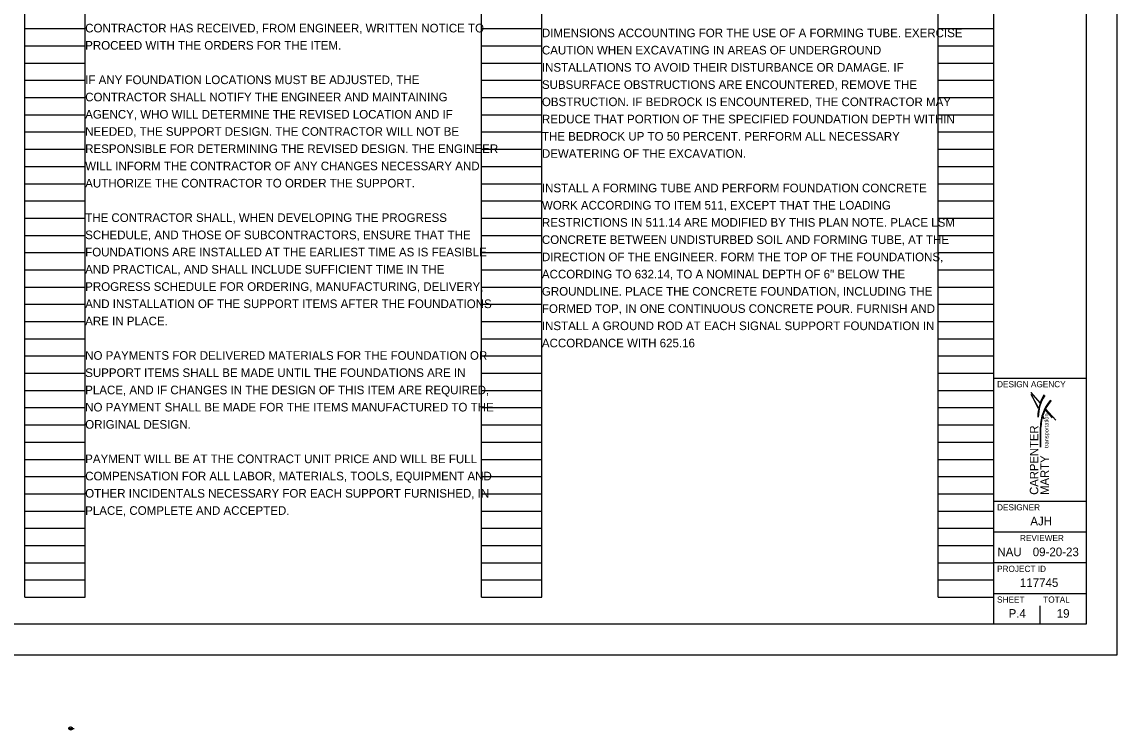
# Model space of a CAD drawing. Extents: x 0 to 34, y -1.2 to 22.
# Drawn here: x 16.21 to 34, y -1.18 to 10.33 of the extents above; entities that cross this region are included whole.
import ezdxf

# ---------------------------------------------------------------- set-up
doc = ezdxf.new("R2010")
doc.units = 0
for name, color, linetype in [('SH_Border', 7, 'Continuous'), ('SH_Cut_Line', 7, 'Continuous'), ('SH_Data', 7, 'Continuous'), ('SH_Text', 7, 'Continuous')]:
    doc.layers.add(name, color=color, linetype=linetype)

msp = doc.modelspace()

# ---------------------------------------------------------------- linework, layer by layer
at = {"layer": 'SH_Border'}
for p, q in [((32.005, 0.541), (32.005, 21.541)), ((32.005, 4.541), (33.505, 4.541)), ((32.005, 2.541), (33.505, 2.541)), ((32.005, 2.041), (33.505, 2.041)), ((32.005, 1.541), (33.505, 1.541)), ((32.005, 1.041), (33.505, 1.041))]:
    msp.add_line(p, q, dxfattribs=at)
msp.add_lwpolyline([(1.505, 21.541), (33.505, 21.541), (33.505, 0.541), (1.505, 0.541)], close=True, dxfattribs=at)
at = {"layer": 'SH_Cut_Line'}
msp.add_lwpolyline([(0.005, 0.041), (34.005, 0.041), (34.005, 22.041), (0.005, 22.041)], close=True, dxfattribs=at)
at = {"layer": 'SH_Data'}
for p, q in [((16.26, 0.98), (16.26, 21.14)), ((17.24, 0.98), (17.24, 21.14)), ((23.68, 0.98), (23.68, 21.14)), ((24.66, 0.98), (24.66, 21.14)), ((31.1, 0.98), (31.1, 21.14)), ((32, 0.98), (32, 21.14)), ((16.26, 10.22), (17.24, 10.22)), ((23.68, 10.22), (24.66, 10.22)), ((31.1, 10.22), (32, 10.22)), ((16.26, 9.94), (17.24, 9.94)), ((23.68, 9.94), (24.66, 9.94)), ((31.1, 9.94), (32, 9.94)), ((16.26, 9.66), (17.24, 9.66)), ((23.68, 9.66), (24.66, 9.66)), ((31.1, 9.66), (32, 9.66)), ((16.26, 9.38), (17.24, 9.38)), ((23.68, 9.38), (24.66, 9.38)), ((31.1, 9.38), (32, 9.38)), ((16.26, 9.1), (17.24, 9.1)), ((23.68, 9.1), (24.66, 9.1)), ((31.1, 9.1), (32, 9.1)), ((16.26, 8.82), (17.24, 8.82)), ((23.68, 8.82), (24.66, 8.82)), ((31.1, 8.82), (32, 8.82)), ((16.26, 8.54), (17.24, 8.54)), ((23.68, 8.54), (24.66, 8.54)), ((31.1, 8.54), (32, 8.54)), ((16.26, 8.26), (17.24, 8.26)), ((23.68, 8.26), (24.66, 8.26)), ((31.1, 8.26), (32, 8.26)), ((16.26, 7.98), (17.24, 7.98)), ((23.68, 7.98), (24.66, 7.98)), ((31.1, 7.98), (32, 7.98)), ((16.26, 7.7), (17.24, 7.7)), ((23.68, 7.7), (24.66, 7.7)), ((31.1, 7.7), (32, 7.7)), ((16.26, 7.42), (17.24, 7.42)), ((23.68, 7.42), (24.66, 7.42)), ((31.1, 7.42), (32, 7.42)), ((16.26, 7.14), (17.24, 7.14)), ((23.68, 7.14), (24.66, 7.14)), ((31.1, 7.14), (32, 7.14)), ((16.26, 6.86), (17.24, 6.86)), ((23.68, 6.86), (24.66, 6.86)), ((31.1, 6.86), (32, 6.86)), ((16.26, 6.58), (17.24, 6.58)), ((23.68, 6.58), (24.66, 6.58)), ((31.1, 6.58), (32, 6.58)), ((16.26, 6.3), (17.24, 6.3)), ((23.68, 6.3), (24.66, 6.3)), ((31.1, 6.3), (32, 6.3)), ((16.26, 6.02), (17.24, 6.02)), ((23.68, 6.02), (24.66, 6.02)), ((31.1, 6.02), (32, 6.02)), ((16.26, 5.74), (17.24, 5.74)), ((23.68, 5.74), (24.66, 5.74)), ((31.1, 5.74), (32, 5.74)), ((16.26, 5.46), (17.24, 5.46)), ((23.68, 5.46), (24.66, 5.46)), ((31.1, 5.46), (32, 5.46)), ((16.26, 5.18), (17.24, 5.18)), ((23.68, 5.18), (24.66, 5.18)), ((31.1, 5.18), (32, 5.18)), ((16.26, 4.9), (17.24, 4.9)), ((23.68, 4.9), (24.66, 4.9)), ((31.1, 4.9), (32, 4.9)), ((16.26, 4.62), (17.24, 4.62)), ((23.68, 4.62), (24.66, 4.62)), ((31.1, 4.62), (32, 4.62)), ((16.26, 4.34), (17.24, 4.34)), ((23.68, 4.34), (24.66, 4.34)), ((31.1, 4.34), (32, 4.34)), ((16.26, 4.06), (17.24, 4.06)), ((23.68, 4.06), (24.66, 4.06)), ((31.1, 4.06), (32, 4.06)), ((16.26, 3.78), (17.24, 3.78)), ((23.68, 3.78), (24.66, 3.78)), ((31.1, 3.78), (32, 3.78)), ((16.26, 3.5), (17.24, 3.5)), ((23.68, 3.5), (24.66, 3.5)), ((31.1, 3.5), (32, 3.5)), ((32.755, 3.541), (32.755, 3.541)), ((16.26, 3.22), (17.24, 3.22)), ((23.68, 3.22), (24.66, 3.22)), ((31.1, 3.22), (32, 3.22)), ((16.26, 2.94), (17.24, 2.94)), ((23.68, 2.94), (24.66, 2.94)), ((31.1, 2.94), (32, 2.94)), ((16.26, 2.66), (17.24, 2.66)), ((23.68, 2.66), (24.66, 2.66)), ((31.1, 2.66), (32, 2.66)), ((16.26, 2.38), (17.24, 2.38)), ((23.68, 2.38), (24.66, 2.38)), ((31.1, 2.38), (32, 2.38)), ((16.26, 2.1), (17.24, 2.1)), ((23.68, 2.1), (24.66, 2.1)), ((31.1, 2.1), (32, 2.1)), ((16.26, 1.82), (17.24, 1.82)), ((23.68, 1.82), (24.66, 1.82)), ((31.1, 1.82), (32, 1.82)), ((16.26, 1.54), (17.24, 1.54)), ((23.68, 1.54), (24.66, 1.54)), ((31.1, 1.54), (32, 1.54)), ((16.26, 1.26), (17.24, 1.26)), ((23.68, 1.26), (24.66, 1.26)), ((31.1, 1.26), (32, 1.26)), ((16.26, 0.98), (17.24, 0.98)), ((23.68, 0.98), (24.66, 0.98)), ((31.1, 0.98), (32, 0.98)), ((32.38, 0.716), (32.38, 0.716)), ((32.755, 0.541), (32.755, 0.841)), ((16.98, -1.154), (17.032, -1.154)), ((17.006, -1.154), (17.059, -1.154))]:
    msp.add_line(p, q, dxfattribs=at)
msp.add_circle((17.006, -1.154), 0.026, dxfattribs=at)
at = {"layer": 'SH_Text'}
for p, q in [((32.726, 4.057), (32.607, 4.273)), ((32.816, 3.881), (32.795, 3.921)), ((32.825, 3.874), (32.796, 3.927)), ((32.957, 3.893), (32.839, 4.032)), ((32.844, 4.042), (33.011, 3.857)), ((32.76, 3.418), (32.76, 3.745)), ((32.767, 3.418), (32.767, 3.745)), ((16.974, -1.152), (17.026, -1.152)), ((17, -1.152), (17.049, -1.152))]:
    msp.add_line(p, q, dxfattribs=at)
for points in [[(32.751, 4.145), (32.606, 4.307)], [(32.606, 4.307), (32.749, 4.139)], [(32.726, 4.057), (32.607, 4.273)], [(32.607, 4.272), (32.724, 4.052)]]:
    msp.add_lwpolyline(points, dxfattribs=at)
msp.add_circle((17, -1.152), 0.026, dxfattribs=at)
for centre, radius, start, end in [((33.437, 3.901), 0.721, 149.5704, 179.5529), ((33.378, 3.902), 0.654, 147.1423, 179.6525), ((33.431, 3.745), 0.671, 139.2898, 180.0106), ((33.438, 3.729), 0.672, 138.5126, 178.6075)]:
    msp.add_arc(centre, radius, start, end, dxfattribs=at)

# ---------------------------------------------------------------- texts
at = {"layer": 'SH_Data'}
for s, height, p in [('DESIGN AGENCY', 0.1, (32.055, 4.391)), ('DESIGNER', 0.1, (32.055, 2.391)), ('AJH', 0.14, (32.595, 2.146)), ('REVIEWER', 0.1, (32.427, 1.891)), ('NAU', 0.14, (32.06, 1.646)), ('09-20-23', 0.14, (32.634, 1.646)), ('PROJECT ID', 0.1, (32.055, 1.391)), ('117745', 0.14, (32.426, 1.146)), ('SHEET', 0.1, (32.055, 0.891)), ('TOTAL', 0.1, (32.805, 0.891)), ('P.4', 0.14, (32.242, 0.646)), ('19', 0.14, (33.024, 0.646)), ('P.4', 0.00328, (17.003, -1.164)), ('2', 0.00328, (17.004, -1.148)), ('Drawing-1', 0.00328, (17.038, -1.148)), ('1:1', 0.00328, (17.038, -1.164))]:
    msp.add_text(s, height=height, dxfattribs=at).set_placement(p)
at = {"layer": 'SH_Text'}
for s, height, p in [('CONTRACTOR HAS RECEIVED, FROM ENGINEER, WRITTEN NOTICE TO ', 0.14, (17.24, 10.158)), ('DIMENSIONS ACCOUNTING FOR THE USE OF A FORMING TUBE. EXERCISE ', 0.14, (24.66, 10.08)), ('PROCEED WITH THE ORDERS FOR THE ITEM. ', 0.14, (17.24, 9.878)), ('CAUTION WHEN EXCAVATING IN AREAS OF UNDERGROUND ', 0.14, (24.66, 9.8)), ('INSTALLATIONS TO AVOID THEIR DISTURBANCE OR DAMAGE. IF ', 0.14, (24.66, 9.52)), ('IF ANY FOUNDATION LOCATIONS MUST BE ADJUSTED, THE ', 0.14, (17.24, 9.318)), ('SUBSURFACE OBSTRUCTIONS ARE ENCOUNTERED, REMOVE THE ', 0.14, (24.66, 9.24)), ('CONTRACTOR SHALL NOTIFY THE ENGINEER AND MAINTAINING ', 0.14, (17.24, 9.038)), ('OBSTRUCTION. IF BEDROCK IS ENCOUNTERED, THE CONTRACTOR MAY ', 0.14, (24.66, 8.96)), ('AGENCY, WHO WILL DETERMINE THE REVISED LOCATION AND IF ', 0.14, (17.24, 8.758)), ('REDUCE THAT PORTION OF THE SPECIFIED FOUNDATION DEPTH WITHIN ', 0.14, (24.66, 8.68)), ('NEEDED, THE SUPPORT DESIGN. THE CONTRACTOR WILL NOT BE ', 0.14, (17.24, 8.478)), ('THE BEDROCK UP TO 50 PERCENT. PERFORM ALL NECESSARY ', 0.14, (24.66, 8.4)), ('RESPONSIBLE FOR DETERMINING THE REVISED DESIGN. THE ENGINEER ', 0.14, (17.24, 8.198)), ('DEWATERING OF THE EXCAVATION.', 0.14, (24.66, 8.12)), ('WILL INFORM THE CONTRACTOR OF ANY CHANGES NECESSARY AND ', 0.14, (17.24, 7.918)), ('AUTHORIZE THE CONTRACTOR TO ORDER THE SUPPORT. ', 0.14, (17.24, 7.638)), ('INSTALL A FORMING TUBE AND PERFORM FOUNDATION CONCRETE ', 0.14, (24.66, 7.56)), ('WORK ACCORDING TO ITEM 511, EXCEPT THAT THE LOADING ', 0.14, (24.66, 7.28)), ('THE CONTRACTOR SHALL, WHEN DEVELOPING THE PROGRESS ', 0.14, (17.24, 7.078)), ('RESTRICTIONS IN 511.14 ARE MODIFIED BY THIS PLAN NOTE. PLACE LSM ', 0.14, (24.66, 7)), ('SCHEDULE, AND THOSE OF SUBCONTRACTORS, ENSURE THAT THE ', 0.14, (17.24, 6.798)), ('CONCRETE BETWEEN UNDISTURBED SOIL AND FORMING TUBE, AT THE ', 0.14, (24.66, 6.72)), ('FOUNDATIONS ARE INSTALLED AT THE EARLIEST TIME AS IS FEASIBLE ', 0.14, (17.24, 6.518)), ('DIRECTION OF THE ENGINEER. FORM THE TOP OF THE FOUNDATIONS, ', 0.14, (24.66, 6.44)), ('AND PRACTICAL, AND SHALL INCLUDE SUFFICIENT TIME IN THE ', 0.14, (17.24, 6.238)), ('ACCORDING TO 632.14, TO A NOMINAL DEPTH OF 6" BELOW THE ', 0.14, (24.66, 6.16)), ('PROGRESS SCHEDULE FOR ORDERING, MANUFACTURING, DELIVERY, ', 0.14, (17.24, 5.958)), ('GROUNDLINE. PLACE THE CONCRETE FOUNDATION, INCLUDING THE ', 0.14, (24.66, 5.88)), ('AND INSTALLATION OF THE SUPPORT ITEMS AFTER THE FOUNDATIONS ', 0.14, (17.24, 5.678)), ('FORMED TOP, IN ONE CONTINUOUS CONCRETE POUR. FURNISH AND ', 0.14, (24.66, 5.6)), ('ARE IN PLACE.', 0.14, (17.24, 5.398)), ('INSTALL A GROUND ROD AT EACH SIGNAL SUPPORT FOUNDATION IN ', 0.14, (24.66, 5.32)), ('ACCORDANCE WITH 625.16', 0.14, (24.66, 5.04)), ('NO PAYMENTS FOR DELIVERED MATERIALS FOR THE FOUNDATION OR ', 0.14, (17.24, 4.838)), ('SUPPORT ITEMS SHALL BE MADE UNTIL THE FOUNDATIONS ARE IN ', 0.14, (17.24, 4.558)), ('PLACE, AND IF CHANGES IN THE DESIGN OF THIS ITEM ARE REQUIRED, ', 0.14, (17.24, 4.278)), ('NO PAYMENT SHALL BE MADE FOR THE ITEMS MANUFACTURED TO THE ', 0.14, (17.24, 3.998)), ('ORIGINAL DESIGN.', 0.14, (17.24, 3.718)), ('PAYMENT WILL BE AT THE CONTRACT UNIT PRICE AND WILL BE FULL ', 0.14, (17.24, 3.158)), ('COMPENSATION FOR ALL LABOR, MATERIALS, TOOLS, EQUIPMENT AND ', 0.14, (17.24, 2.878)), ('OTHER INCIDENTALS NECESSARY FOR EACH SUPPORT FURNISHED, IN ', 0.14, (17.24, 2.598)), ('PLACE, COMPLETE AND ACCEPTED.', 0.14, (17.24, 2.318)), ('P.4', 0.00328, (16.997, -1.162)), ('1', 0.00328, (16.999, -1.146)), ('Drawing', 0.00328, (17.032, -1.146)), ('1:1', 0.00328, (17.032, -1.162))]:
    msp.add_text(s, height=height, dxfattribs=at).set_placement(p)
for s, height, p in [('transportation', 0.06649, (32.89, 3.405)), ('CARPENTER ', 0.1367, (32.724, 2.643)), ('MARTY', 0.1367, (32.896, 2.643))]:
    msp.add_text(s, height=height, rotation=90, dxfattribs=at).set_placement(p)

doc.saveas('drawing.dxf')
